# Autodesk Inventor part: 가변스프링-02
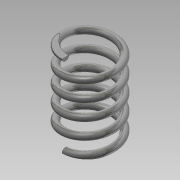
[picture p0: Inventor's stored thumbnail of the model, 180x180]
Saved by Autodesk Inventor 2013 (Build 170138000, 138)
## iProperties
Created: 2014-12
Part Number: 가변스프링-02
Material: 강철, 탄소
Document SubType Name: Modeling
Designer: hanacad19
Density: 7.87 g/cm^3
Mass: 18.8932 g
Surface Area: 32.5247 cm^2
Volume: 2.40066 cm^3
Author: hanacad19
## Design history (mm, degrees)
sketch "스케치1"
  geometry: L1 (0, 0)-(-11, 0); L2 (-11, 0)-(-11, 36.411); L3 (-11, 36.411)-(0, 36.411); L4 (0, 36.411)-(0, 0); C1 r 1.5 at (-11, 0)
  constraints: 8 end point, 2 parallel, 1 centre point, 1 horizontal, 1 perpendicular
  dimensions: "d0" = 3 diameter of C1; "d2" = 22 diameter of L2 L4; "d3" = 36.4112 distance between parallel lines of L1 L3 (derived)
feature "코일1" sketch "스케치1" pitch "d4" = 10; turns "d6" = 5; dims "d5" = 36.4112 (= d3), "d7" = 0, angle "d8" = 90 deg, angle "d9" = 90 deg, "d10" = 0, "d11" = 0
sketch "스케치2"
  geometry: L1 (0, -12.5)-(0, -9.5) reference; 1 further point
  constraints: 1 vertical alignment
extrude "돌출1" cut sketch "스케치2" distance "d12" = 10; taper "d13" = 0 deg
node "작업 평면1"
sketch "스케치3"
  geometry: L1 (0, -9.5)-(0, -12.5) reference; 1 further point
  constraints: 1 vertical alignment
extrude "돌출2" cut sketch "스케치3" distance "d14" = 10; taper "d15" = 0 deg
node "솔리드1"
node "절단 모서리 투영1"
node "절단 모서리 투영2"
